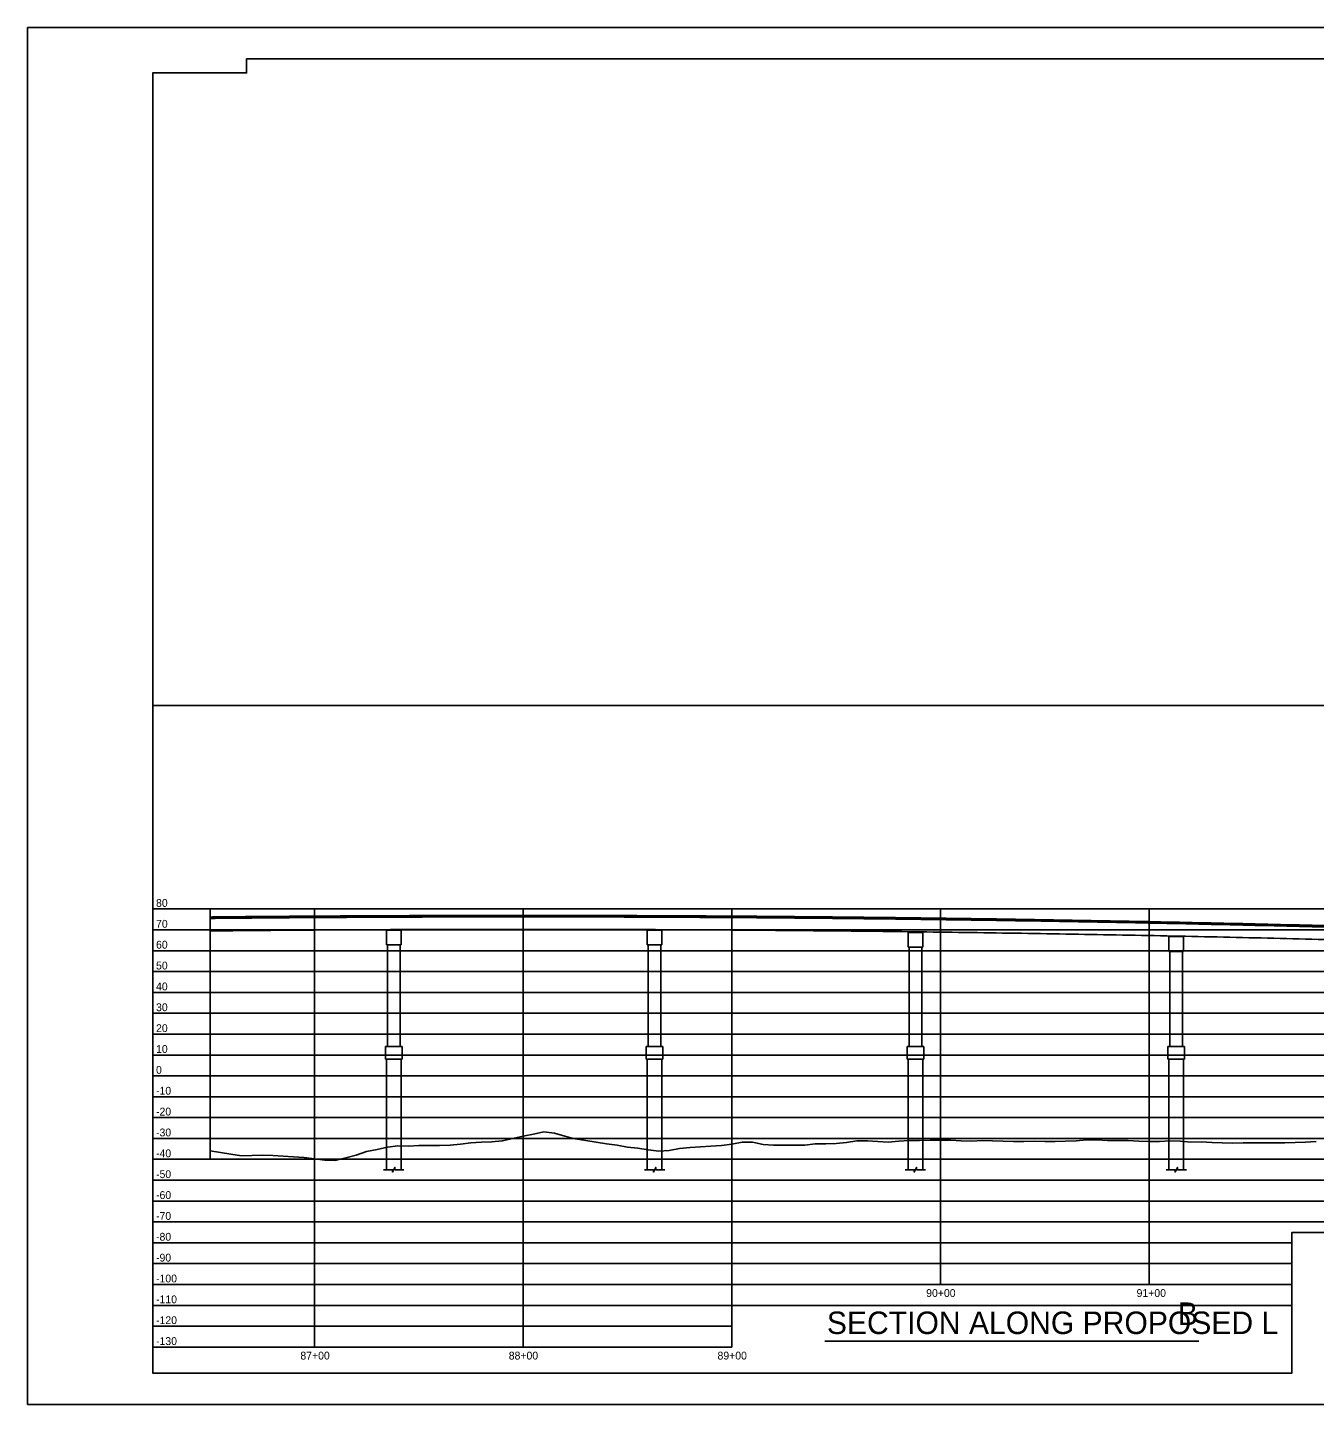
# Model space of a CAD drawing. Extents: x -464 to 4306, y -1372 to 300.
# Drawn here: x 1996 to 2613, y -1372 to -712 of the extents above; entities that cross this region are included whole.
import ezdxf

# ---------------------------------------------------------------- set-up
doc = ezdxf.new("R2010")
doc.units = 0
for name, color, linetype in [('BR_AUTO DIMENSION', 7, 'Continuous'), ('BR_BORDER LINES', 7, 'Continuous'), ('BR_GRID LINES', 7, 'Continuous'), ('BR_TEXT', 7, 'Continuous'), ('Mis Ground Lines', 7, 'Continuous'), ('NOPLOT', 7, 'Continuous'), ('Sheet Plot Border Outside CELL', 7, 'Continuous'), ('sub interior bent cap lines', 7, 'Continuous'), ('Sup Concrete Girder Lines', 7, 'Continuous'), ('Sup Concrete Slab Lines', 7, 'Continuous')]:
    doc.layers.add(name, color=color, linetype=linetype)

msp = doc.modelspace()

# ---------------------------------------------------------------- linework, layer by layer
at = {"layer": 'BR_AUTO DIMENSION'}
msp.add_line((2083.5, -1254.94), (2083.5, -1134.94), dxfattribs=at)
for points in [[(2166.62, -1259.94), (2170.94, -1259.94), (2170.94, -1261.06), (2172.06, -1258.83), (2172.06, -1259.94), (2176.37, -1259.94)], [(2291.62, -1259.94), (2295.94, -1259.94), (2295.94, -1261.06), (2297.06, -1258.83), (2297.06, -1259.94), (2301.37, -1259.94)], [(2416.62, -1259.94), (2420.94, -1259.94), (2420.94, -1261.06), (2422.06, -1258.83), (2422.06, -1259.94), (2426.37, -1259.94)], [(2541.62, -1259.94), (2545.94, -1259.94), (2545.94, -1261.06), (2547.06, -1258.83), (2547.06, -1259.94), (2551.37, -1259.94)]]:
    msp.add_lwpolyline(points, dxfattribs=at)
at = {"layer": 'BR_BORDER LINES'}
msp.add_line((2056, -1037.44), (3061, -1037.44), dxfattribs=at)
at = {"layer": 'BR_GRID LINES'}
for p, q in [((2056, -1134.94), (3061, -1134.94)), ((2133.5, -1344.94), (2133.5, -1134.94)), ((2233.5, -1344.94), (2233.5, -1134.94)), ((2333.5, -1344.94), (2333.5, -1134.94)), ((2433.5, -1314.94), (2433.5, -1134.94)), ((2533.5, -1314.94), (2533.5, -1134.94)), ((2056, -1144.94), (3061, -1144.94)), ((2056, -1154.94), (3061, -1154.94)), ((2056, -1164.94), (3061, -1164.94)), ((2056, -1174.94), (3061, -1174.94)), ((2056, -1184.94), (3061, -1184.94)), ((2056, -1194.94), (3061, -1194.94)), ((2056, -1204.94), (3061, -1204.94)), ((2056, -1214.94), (3061, -1214.94)), ((2056, -1224.94), (3061, -1224.94)), ((2056, -1234.94), (3061, -1234.94)), ((2056, -1244.94), (3061, -1244.94)), ((2056, -1254.94), (3061, -1254.94)), ((2056, -1264.94), (3061, -1264.94)), ((2056, -1274.94), (2836, -1274.94)), ((2056, -1284.94), (2836, -1284.94)), ((2056, -1294.94), (2601.93, -1294.94)), ((2056, -1304.94), (2601.93, -1304.94)), ((2056, -1314.94), (2601.93, -1314.94)), ((2056, -1324.94), (2601.93, -1324.94)), ((2056, -1334.94), (2333.5, -1334.94)), ((2056, -1344.94), (2333.5, -1344.94))]:
    msp.add_line(p, q, dxfattribs=at)
at = {"layer": 'BR_TEXT'}
msp.add_line((2378.09, -1342.1), (2557.35, -1342.1), dxfattribs=at)
at = {"layer": 'Mis Ground Lines'}
for points in [[(2083.5, -1250.87), (2088.5, -1251.63), (2093.5, -1252.44), (2098.5, -1253.2), (2103.5, -1253.12), (2108.5, -1252.92), (2113.5, -1253.08), (2118.5, -1253.46), (2123.5, -1253.74), (2128.5, -1254.03), (2133.5, -1254.67), (2138.5, -1255.36), (2143.5, -1255.48), (2148.5, -1254.29), (2153.5, -1252.88), (2158.5, -1251.26), (2163.5, -1250.16), (2168.5, -1249.04), (2173.5, -1248.53), (2178.5, -1248.56), (2183.5, -1248.34), (2188.5, -1248.28), (2193.5, -1248.31), (2198.5, -1248.19), (2203.5, -1247.71), (2208.5, -1246.97), (2213.5, -1246.76), (2218.5, -1246.52), (2223.5, -1246.13), (2228.5, -1245), (2233.5, -1243.87), (2238.5, -1242.82), (2243.5, -1241.75), (2248.5, -1242.39), (2253.5, -1243.88), (2258.5, -1245.17), (2263.5, -1245.99), (2268.5, -1246.76), (2273.5, -1247.52), (2278.5, -1248.23), (2283.5, -1249.07), (2288.5, -1249.57), (2293.5, -1250.4), (2298.5, -1250.96), (2303.5, -1250.67), (2308.5, -1249.81), (2313.5, -1249.35), (2318.5, -1248.99), (2323.5, -1248.63), (2328.5, -1248.27), (2333.5, -1247.6), (2338.5, -1246.66), (2343.5, -1246.72), (2348.5, -1247.76), (2353.5, -1248.19), (2358.5, -1248.08), (2363.5, -1248.15), (2368.5, -1248.17), (2373.5, -1247.51), (2378.5, -1247.49), (2383.5, -1247.29), (2388.5, -1246.8), (2393.5, -1246.11), (2398.5, -1246.09), (2403.5, -1246.4), (2408.5, -1246.72), (2413.5, -1246.31), (2418.5, -1245.92), (2423.5, -1245.96), (2428.5, -1245.83), (2433.5, -1245.76)], [(2433.5, -1245.76), (2438.5, -1245.71), (2443.5, -1246.01), (2448.5, -1246.24), (2453.5, -1245.98), (2458.5, -1246.01), (2463.5, -1246.24), (2468.5, -1246.34), (2473.5, -1246.36), (2478.5, -1246.3), (2483.5, -1246.35), (2488.5, -1246.38), (2493.5, -1246.22), (2498.5, -1246.04), (2503.5, -1245.64), (2508.5, -1245.66), (2513.5, -1245.85), (2518.5, -1245.89), (2523.5, -1245.99), (2528.5, -1246.26), (2533.5, -1246.37), (2538.5, -1246.37), (2543.5, -1246.15), (2548.5, -1246.27), (2553.5, -1246.69), (2558.5, -1246.62), (2563.5, -1246.93), (2568.5, -1247.08), (2573.5, -1247.14), (2578.5, -1247.09), (2583.5, -1247.1), (2588.5, -1247.02), (2593.5, -1247.07), (2598.5, -1247.08), (2603.5, -1246.95), (2608.5, -1246.72), (2613.5, -1246.4)]]:
    msp.add_lwpolyline(points, dxfattribs=at)
at = {"layer": 'NOPLOT'}
msp.add_lwpolyline([(2101, -727.45), (2101, -734.19), (2056, -734.19), (2056, -1357.44), (2601.93, -1357.44), (2601.93, -1289.94), (2836, -1289.94), (2836, -1274.94), (3061, -1274.94), (3061, -747.45), (2986, -747.45), (2986, -727.45)], close=True, dxfattribs=at)
at = {"layer": 'Sheet Plot Border Outside CELL'}
msp.add_lwpolyline([(1996, -712.44), (3076, -712.44), (3076, -1372.44), (1996, -1372.44)], close=True, dxfattribs=at)
at = {"layer": 'sub interior bent cap lines'}
for p, q in [((2175, -1145.16), (2168, -1145.19)), ((2168, -1145.19), (2168, -1152.17)), ((2175, -1145.16), (2175, -1152.17)), ((2293, -1145.16), (2293, -1152.18)), ((2300, -1145.19), (2293, -1145.16)), ((2300, -1145.19), (2300, -1152.18)), ((2418, -1146.17), (2418, -1153.21)), ((2425, -1146.26), (2418, -1146.17)), ((2425, -1146.26), (2425, -1153.21)), ((2543, -1148.21), (2543, -1155.28)), ((2550, -1148.36), (2543, -1148.21)), ((2550, -1148.36), (2550, -1155.28)), ((2168, -1152.17), (2175, -1152.17)), ((2168.5, -1152.17), (2168.5, -1200.94)), ((2174.5, -1152.17), (2174.5, -1200.94)), ((2293, -1152.18), (2300, -1152.18)), ((2293.5, -1152.18), (2293.5, -1200.94)), ((2299.5, -1152.18), (2299.5, -1200.94)), ((2418, -1153.21), (2425, -1153.21)), ((2418.5, -1153.21), (2418.5, -1200.94)), ((2424.5, -1153.21), (2424.5, -1200.94)), ((2543, -1155.28), (2550, -1155.28)), ((2543.5, -1155.28), (2543.5, -1200.94)), ((2549.5, -1155.28), (2549.5, -1200.94)), ((2167.5, -1200.94), (2175.5, -1200.94)), ((2167.5, -1200.94), (2167.5, -1206.94)), ((2175.5, -1200.94), (2175.5, -1206.94)), ((2292.5, -1200.94), (2300.5, -1200.94)), ((2292.5, -1200.94), (2292.5, -1206.94)), ((2300.5, -1200.94), (2300.5, -1206.94)), ((2417.5, -1200.94), (2425.5, -1200.94)), ((2417.5, -1200.94), (2417.5, -1206.94)), ((2425.5, -1200.94), (2425.5, -1206.94)), ((2542.5, -1200.94), (2550.5, -1200.94)), ((2542.5, -1200.94), (2542.5, -1206.94)), ((2550.5, -1200.94), (2550.5, -1206.94)), ((2167.5, -1206.94), (2175.5, -1206.94)), ((2168, -1206.94), (2168, -1259.94)), ((2175, -1206.94), (2175, -1259.94)), ((2292.5, -1206.94), (2300.5, -1206.94)), ((2293, -1206.94), (2293, -1259.94)), ((2300, -1206.94), (2300, -1259.94)), ((2417.5, -1206.94), (2425.5, -1206.94)), ((2418, -1206.94), (2418, -1259.94)), ((2425, -1206.94), (2425, -1259.94)), ((2542.5, -1206.94), (2550.5, -1206.94)), ((2543, -1206.94), (2543, -1259.94)), ((2550, -1206.94), (2550, -1259.94))]:
    msp.add_line(p, q, dxfattribs=at)
at = {"layer": 'Sup Concrete Girder Lines'}
for points in [[(2083.5, -1139.45), (2088.31, -1139.41), (2112.51, -1139.2), (2136.7, -1139.02), (2160.9, -1138.89), (2185.1, -1138.79), (2209.3, -1138.73), (2233.5, -1138.71), (2257.7, -1138.73), (2281.9, -1138.79), (2306.1, -1138.89), (2330.3, -1139.02), (2354.49, -1139.2), (2378.69, -1139.41), (2402.89, -1139.66), (2427.09, -1139.95), (2451.29, -1140.28), (2475.49, -1140.65), (2499.69, -1141.05), (2523.89, -1141.5), (2548.09, -1141.98), (2572.29, -1142.51), (2596.48, -1143.07), (2620.68, -1143.67), (2644.88, -1144.31), (2669.08, -1144.98), (2693.28, -1145.7), (2717.48, -1146.45), (2741.68, -1147.25), (2765.88, -1148.08), (2790.08, -1148.95), (2814.27, -1149.86), (2838.47, -1150.81)], [(2083.5, -1145.46), (2088.36, -1145.41), (2112.55, -1145.19), (2136.74, -1145.02), (2160.93, -1144.89), (2185.12, -1144.79), (2209.31, -1144.73), (2233.5, -1144.71), (2257.69, -1144.73), (2281.88, -1144.79), (2306.07, -1144.89), (2330.26, -1145.02), (2354.45, -1145.19), (2378.64, -1145.41), (2402.83, -1145.66), (2427.01, -1145.95), (2451.2, -1146.28), (2475.39, -1146.65), (2499.58, -1147.05), (2523.77, -1147.5), (2547.96, -1147.98), (2572.15, -1148.5), (2596.34, -1149.07), (2620.53, -1149.67), (2644.72, -1150.3), (2668.91, -1150.98), (2693.1, -1151.7), (2717.29, -1152.45), (2741.48, -1153.25), (2765.67, -1154.08), (2789.85, -1154.95), (2814.04, -1155.86), (2838.23, -1156.81)]]:
    msp.add_spline(points, degree=3, dxfattribs=at)
at = {"layer": 'Sup Concrete Slab Lines'}
msp.add_spline([(2083.5, -1138.79), (2088.3, -1138.74), (2112.5, -1138.53), (2136.7, -1138.35), (2160.9, -1138.22), (2185.1, -1138.12), (2209.3, -1138.06), (2233.5, -1138.04), (2257.7, -1138.06), (2281.9, -1138.12), (2306.1, -1138.22), (2330.3, -1138.35), (2354.5, -1138.53), (2378.7, -1138.74), (2402.9, -1138.99), (2427.1, -1139.28), (2451.3, -1139.61), (2475.5, -1139.98), (2499.7, -1140.39), (2523.9, -1140.83), (2548.1, -1141.32), (2572.3, -1141.84), (2596.5, -1142.4), (2620.7, -1143), (2644.9, -1143.64), (2669.1, -1144.32), (2693.3, -1145.03), (2717.5, -1145.79), (2741.7, -1146.58), (2765.9, -1147.41), (2790.1, -1148.29), (2814.3, -1149.2), (2838.5, -1150.14)], degree=3, dxfattribs=at)

# ---------------------------------------------------------------- texts
at = {"layer": 'BR_TEXT'}
for s, p in [('80', (2057.58, -1133.94)), ('70', (2057.58, -1143.94)), ('60', (2057.58, -1153.94)), ('50', (2057.58, -1163.94)), ('40', (2057.58, -1173.94)), ('30', (2057.58, -1183.94)), ('20', (2057.58, -1193.94)), ('10', (2057.58, -1203.94)), ('0', (2057.58, -1213.94)), ('-10', (2057.58, -1223.94)), ('-20', (2057.58, -1233.94)), ('-30', (2057.58, -1243.94)), ('-40', (2057.58, -1253.94)), ('-50', (2057.58, -1263.94)), ('-60', (2057.58, -1273.94)), ('-70', (2057.58, -1283.94)), ('-80', (2057.58, -1293.94)), ('-90', (2057.58, -1303.94)), ('-100', (2057.58, -1313.94)), ('90+00', (2426.66, -1320.91)), ('91+00', (2527.49, -1320.91)), ('-110', (2057.58, -1323.94)), ('-120', (2057.58, -1333.94)), ('-130', (2057.58, -1343.94)), ('87+00', (2126.75, -1350.91)), ('88+00', (2226.61, -1350.91)), ('89+00', (2326.66, -1350.91))]:
    msp.add_text(s, height=3.75, rotation=360, dxfattribs=at).set_placement(p)
for s, height, p in [('B', 10.78, (2547.24, -1334.33)), ('SECTION ALONG PROPOSED L', 10.7809, (2379.07, -1338.69))]:
    msp.add_text(s, height=height, dxfattribs=at).set_placement(p)

doc.saveas('drawing.dxf')
